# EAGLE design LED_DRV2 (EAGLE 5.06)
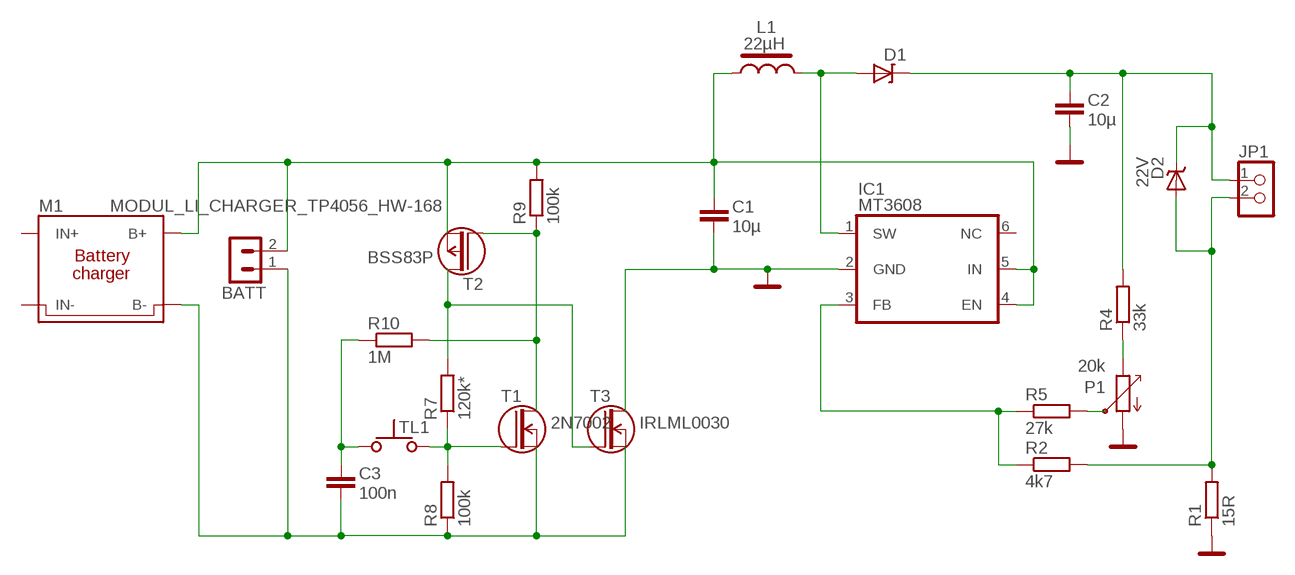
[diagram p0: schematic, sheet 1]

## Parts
BATT  KONZ-02JST-XH  [JST-XH2]
C1  10µ  CSMD1210  [C1210K]
C2  10µ  CSMD1210  [C1210K]
C3  100n  CSMD0805_KEMET_REFLOW  [C0805K]
D1  DIODA-SCHOTTKYSMB  [SMB]
D2  22V  TRANSIL_SMA(B?)  [SMA(B)]
IC1  MT3608_R  [SOT23-6(R)]
JP1  PINHD-1X2  [1X02]
L1  22µH  TLUMIVKA_UNI8X8  [TLUMIVKA_SMD_UNI8X8]
M1  MODUL_LI_CHARGER_TP4056_HW-168  [MODUL_LI_CHARGER-HW-168]
P1  20k  POTENCIOMETR_RV09  [POT_RV09-MONO]
R1  15R  REZISTOR_SMD0805_KEMET_REFLOW  [C0805K]
R2  4k7  REZISTOR_SMD0805_KEMET_REFLOW  [C0805K]
R4  33k  REZISTOR_SMD0805_KEMET_REFLOW  [C0805K]
R5  27k  REZISTOR_SMD0805_KEMET_REFLOW  [C0805K]
R7  120k*  REZISTOR_SMD0805_KEMET_REFLOW  [C0805K]
R8  100k  REZISTOR_SMD0805_KEMET_REFLOW  [C0805K]
R9  100k  REZISTOR_SMD0805_KEMET_REFLOW  [C0805K]
R10  1M  REZISTOR_SMD0805_KEMET_REFLOW  [C0805K]
T1  2N7002  T_NFETSOT23  [SOT23-R]
T2  BSS83P  T_PFETSOT23  [SOT23-R]
T3  IRLML0030  T_NFETSOT23  [SOT23-R]
TL1  TLACITKOP-B1720  [P-B1720]

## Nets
B-: BATT.1 C3.2 M1.B- R8.1 T1.E(S) T3.E(S)
GND: C1.2 C2.2 IC1.2(GND) P1.E R1.1 T3.C(D)
N$16: C2.1 D1.K D2.K JP1.1 R4.2
N$17: C3.1 R10.1 TL1.1
N$18: P1.S R4.1
N$19: IC1.3(FB) R2.1 R5.1
N$20: P1.T R5.2
N$22: D1.A IC1.1(SW) L1.F2
N$23: R7.1 R8.2 T1.B(G) TL1.2
N$25: BATT.2 C1.1 IC1.4(EN) IC1.5(IN) L1.F1 M1.B+ R9.2 T2.E(S)
N$26: R7.2 T2.C(D) T3.B(G)
N$27: R9.1 R10.2 T1.C(D) T2.B(G)
N$30: D2.A JP1.2 R1.2 R2.2
Unconnected: IC1.6(NC) TL1.3 TL1.4

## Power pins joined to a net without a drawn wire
IN+: M1.IN+
IN-: M1.IN-

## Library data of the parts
BATT = #bcs_pinhead:KONZ-02: Konektory se zamkem - vidlice - 2pin
C1-C3 = #bcs7d:C: Kondenzatory, keramicke a foliove
D1 = #bcs7d:DIODA-SCHOTTKY
D2 = #bcs7d:TRANSIL: Transient voltage suppressor - TRANSIL
IC1 = #bcs-ic1:MT3608
JP1 = #bcs_pinhead:PINHD-1X2: PIN HEADER
L1 = #bcs7d:TLUMIVKA_: Tlumivka
M1 = #bcs_special:MODUL_LI_CHARGER_TP4056
P1 = #bcs7d:POTENCIOMETR
R1 R2 R4 R5 R7-R10 = #bcs7d:REZISTOR_
T1 T3 = #bcs7d:T_NFET: N-FET
T2 = #bcs7d:T_PFET
TL1 = #bcs7d:TLACITKO

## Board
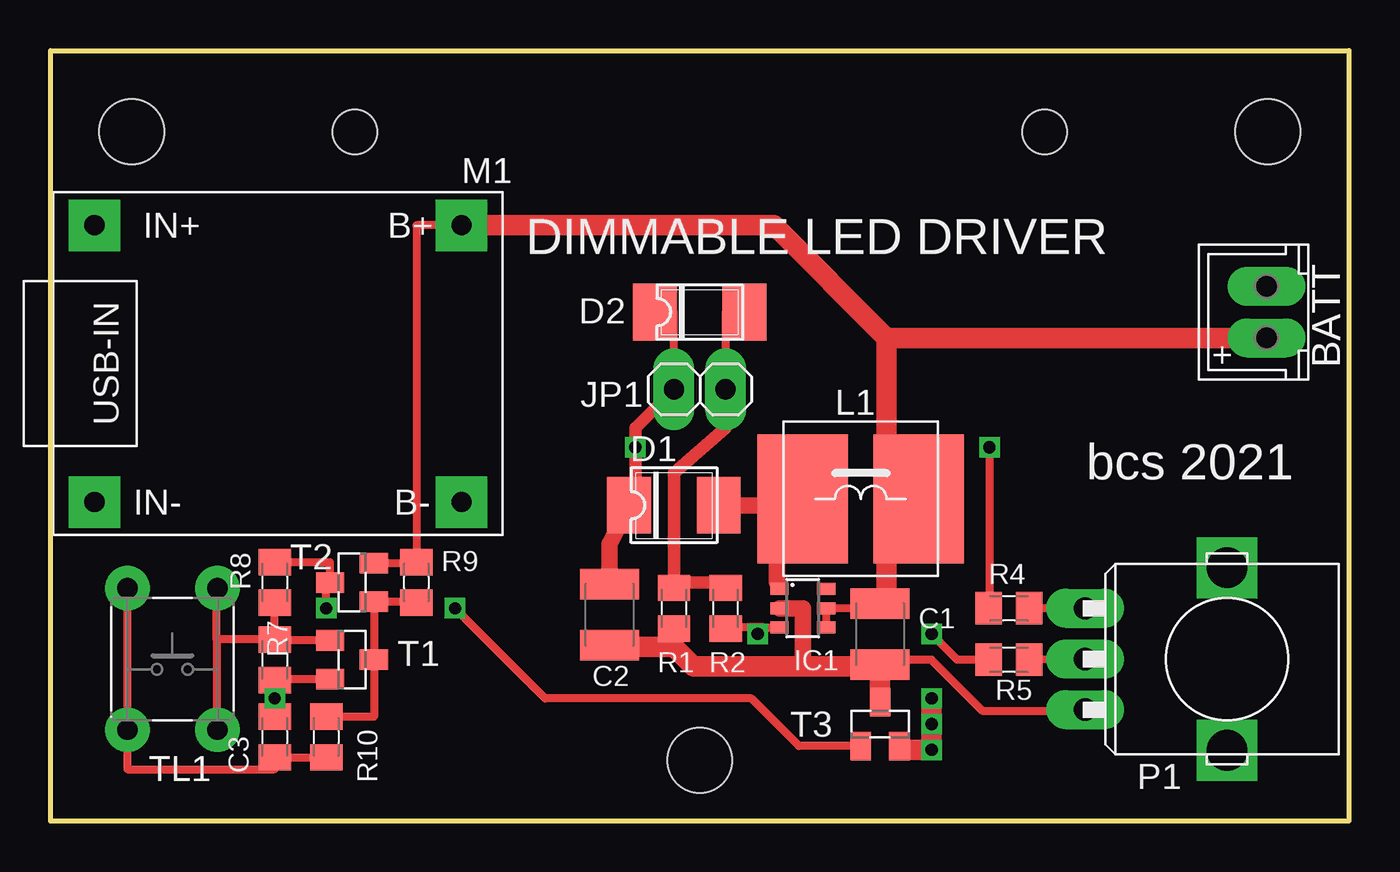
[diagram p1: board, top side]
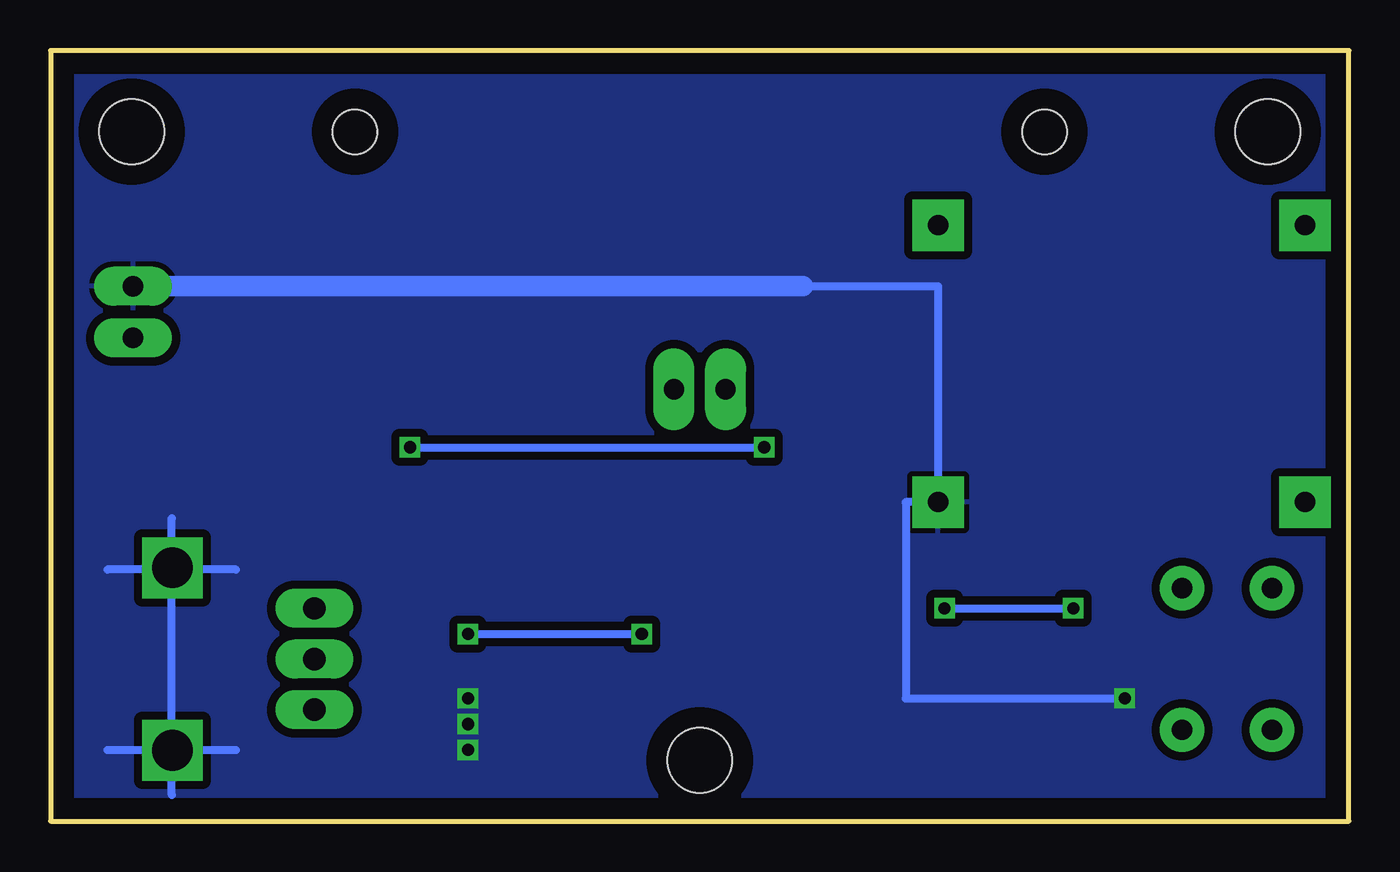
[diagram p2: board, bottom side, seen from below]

Size 64 x 38 mm. Coordinates in mm from the lower left corner, seen from the top.
Outline: 0,0 0,38 64,38 64,0 0,0
Copper layers (1*16): Top 0.035mm / dielectric 1.5mm / Bottom 0.035mm
Design rules "default": minimum track width 10mil, minimum drill 24mil, track to track 8mil, track to pad 8mil, pad to pad 8mil, via to via 8mil, smd to smd 8mil, copper to edge 40mil, drill to drill 8mil, minimum pad ring 10mil, minimum via ring 8mil, stop-mask expansion 4mil, vias tented up to drill 0mil, thermal gap 10mil
Holes 2.2 mm at 49,34 15,34
Holes 3.2 mm at 60,34 4,34 32,3

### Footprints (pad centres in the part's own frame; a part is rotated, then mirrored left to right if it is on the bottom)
JST-XH2 = drill 1 pad 1.93 long: 1 -1.27,0; 2 1.27,0
C1210K = smd 1.5 x 2.9: 1 -1.5,0; 2 1.5,0
C0805K = smd 1.3 x 1.6: 1 -1,0; 2 1,0
SMB = smd 2.159 x 2.794: A 2.21,0; K -2.21,0
SMA(B) = smd 2.159 x 2.794: A 2.21,0; K -2.21,0
SOT23-6(R) = smd 0.6 x 0.9: 1 -0.95,-1.15; 2 0,-1.15; 3 0.95,-1.15; 4 0.95,1.15; 5 0,1.15; 6 -0.95,1.15
1X02 = drill 1 pad 2.032 long: 1 -1.27,0; 2 1.27,0
TLUMIVKA_SMD_UNI8X8 = smd 4.445 x 6.35: F1 2.857,0; F2 -2.857,0
MODUL_LI_CHARGER-HW-168 = drill 1 pad 2.54 square: B+ 18.415,6.826; B- 18.415,-6.826; IN+ 0.318,6.826; IN- 0.318,-6.826
POT_RV09-MONO = drill 1.1 pad 1.93 long: E 2.5,-7; S -2.5,-7; T 0,-7 | drill 2 pad 3 square: P$1 -4.5,0; P$2 4.5,0
SOT23-R = smd 1.016 x 1.397: B -0.953,-1.079; C 0,1.079; E 0.953,-1.079
P-B1720 = drill 1 pad 2.184 round: 1 -3.493,-2.223; 2 -3.493,2.223; 3 3.493,-2.223; 4 3.493,2.223

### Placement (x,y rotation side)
BATT  59.94,25.11 270 top
C1  40.89,9.23 270 top
C2  27.55,10.19 270 top
C3  11.05,4.16 90 top
D1  30.73,15.59 0 top
D2  32,25.11 0 top
IC1  37.08,10.5 270 top
JP1  32,21.3 0 top
L1  39.94,15.9 0 top
M1  1.84,22.57 0 top
P1  58,8 270 top
R1  30.73,10.5 90 top
R2  33.27,10.5 90 top
R4  47.24,10.5 180 top
R5  47.24,7.96 0 top
R7  11.05,11.77 90 top
R8  11.05,7.96 90 top
R9  18.03,11.77 90 top
R10  13.59,4.16 90 top
T1  14.86,7.96 270 top
T2  14.86,11.77 90 top
T3  40.89,4.79 0 top
TL1  6,8 270 top

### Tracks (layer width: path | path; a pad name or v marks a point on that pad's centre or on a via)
B-  (via drill 0.6)
  Top 0.406: C3.2 v11.05,6.06 R8.1 11.05,7.01 T1.E
  Top 1.016: 42.16,3.52 T3.E | 42.16,3.52 41.84,3.52 | 42.16,3.52 v43.43,3.52 v43.43,4.79 v43.43,6.06
  Bottom 0.406: v11.05,6.06 21.84,6.06 21.84,15.74 M1.B- 20.25,26.38 26.92,26.38 | 54.86,12.41 61.21,12.41 | 58.03,1.3 58.03,14.95 | 61.21,3.52 54.86,3.52
  Bottom 1.016: 26.92,26.38 BATT.1
  pour Bottom (isolate 0.406): 0.25,37.81 63.75,37.81 63.75,0.34 0.25,0.34
GND
  Top 0.406: P1.E 50.1,5.43 45.97,5.43 43.43,7.96 41.21,7.96 40.89,7.65 | 27.55,8.6 C2.2 | 30.73,8.6 R1.1
  Top 0.813: 40.89,7.65 C1.2 | IC1.2 37.08,10.5 37.08,7.65
  Top 1.016: 27.55,8.6 30.73,8.6 31.68,7.65 37.08,7.65 40.89,7.65 T3.C
N$16  (via drill 0.6)
  Top 0.406: R4.2 46.29,10.5 v46.29,18.44 | D2.K 30.73,25.11 JP1.1
  Top 0.61: 28.19,15.6 28.19,16.22 28.82,16.22 v28.82,18.44 28.82,19.39 JP1.1
  Top 0.813: C2.1 27.55,13.68 D1.K 28.19,15.6
  Bottom 0.406: v46.29,18.44 v28.82,18.44
N$17
  Top 0.406: TL1.1 3.78,2.57 11.05,2.57 C3.1 R10.1
N$18
  Top 0.406: P1.S R4.1
N$19  (via drill 0.6)
  Top 0.406: 35.17,9.55 IC1.3 | 35.17,9.55 33.27,9.55 R2.1 | v34.86,9.23 35.17,9.55 | v43.43,9.23 44.7,7.96 R5.1
  Bottom 0.406: v43.43,9.23 v34.86,9.23
N$20
  Top 0.406: P1.T R5.2
N$22
  Top 0.406: IC1.1 35.81,11.45 35.81,11.77 | L1.F2 35.81,15.59
  Top 0.813: D1.A 35.81,15.59 35.81,11.77
N$23
  Top 0.406: T1.B 11.05,8.92 R8.2 | R8.2 R7.1 | TL1.2 8.19,11.49 8.19,8.92 | 8.19,8.92 8.19,4.47 | R8.2 8.19,8.96 8.19,8.92
N$25
  Top 0.406: IC1.4 IC1.5 41.21,10.5 C1.1 | T2.E 18.03,12.73 R9.2 18.03,29.4 M1.B+
  Top 1.016: 41.21,23.84 BATT.2 | 41.21,23.84 41.21,15.9 | 41.21,15.9 L1.F1 | 41.21,15.9 41.21,10.5 | M1.B+ 35.65,29.4 41.21,23.84
N$26  (via drill 0.6)
  Top 0.406: R7.2 13.78,12.77 T2.C 13.59,11.77 v13.59,10.5 | v19.94,10.5 24.38,6.06 34.54,6.06 36.89,3.71 T3.B
  Bottom 0.406: v19.94,10.5 v13.59,10.5
N$27
  Top 0.406: R9.1 18.03,10.82 T2.B T1.C 15.93,5.16 R10.2
N$30
  Top 0.406: 30.73,11.77 R1.2 | D2.A 33.27,25.11 JP1.2
  Top 0.61: R2.2 33.27,11.77 30.73,11.77 30.73,17.17 33.27,19.39 JP1.2

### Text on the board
tNames: DIMMABLE LED DRIVER | bcs 2021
